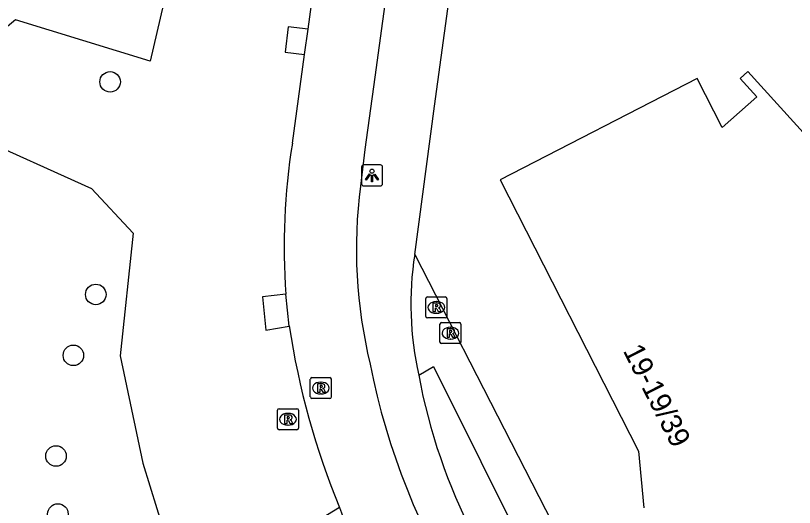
# Model space of a CAD drawing. Extents: x 161402 to 161933, y 381650 to 382313.
# Drawn here: x 161742.85 to 161779.97, y 381978.33 to 382001.78 of the extents above; entities that cross this region are included whole.
import ezdxf

# ---------------------------------------------------------------- set-up
doc = ezdxf.new("R2010")
doc.units = 0
for name, color, linetype in [('IMGEO_Boom', 7, 'Continuous'), ('IMGEO_Groenvoorziening', 7, 'Continuous'), ('IMGEO_Lichtpunt', 7, 'Continuous'), ('IMGEO_Pand', 7, 'Continuous'), ('IMGEO_Pand_nummerreeks', 7, 'Continuous'), ('IMGEO_Rijbaan_lokaal_open', 7, 'Continuous'), ('IMGEO_Rioolput', 7, 'Continuous'), ('IMGEO_Voetpad_open', 7, 'Continuous')]:
    doc.layers.add(name, color=color, linetype=linetype)

msp = doc.modelspace()

# ---------------------------------------------------------------- linework, layer by layer
at = {"layer": 'IMGEO_Boom'}
for centre in [(161747.35, 381998.619), (161746.668, 381988.486), (161745.601, 381985.582), (161744.773, 381980.783), (161744.864, 381978.019)]:
    msp.add_circle(centre, 0.489, dxfattribs=at)
at = {"layer": 'IMGEO_Groenvoorziening'}
msp.add_lwpolyline([(161752.007, 382011.44), (161749.264, 381999.612), (161742.845, 382001.573), (161740.844, 381999.927), (161740.748, 381996.108), (161746.467, 381993.537), (161748.45, 381991.402), (161747.827, 381985.564), (161748.917, 381980.449), (161750.906, 381973.96)], dxfattribs=at)
at = {"layer": 'IMGEO_Lichtpunt'}
for p, q in [((161759.338, 381994.563), (161759.338, 381993.756)), ((161759.338, 381994.563), (161759.338, 381993.756)), ((161760.24, 381994.658), (161759.432, 381994.658)), ((161760.24, 381994.658), (161759.432, 381994.658)), ((161760.334, 381993.756), (161760.334, 381994.563)), ((161760.334, 381993.756), (161760.334, 381994.563)), ((161759.432, 381993.662), (161760.24, 381993.662)), ((161759.432, 381993.662), (161760.24, 381993.662))]:
    msp.add_line(p, q, dxfattribs=at)
for points in [[(161759.712, 381994.227), (161759.751, 381994.199), (161759.563, 381993.937), (161759.525, 381993.964), (161759.712, 381994.227)], [(161759.814, 381994.179), (161759.861, 381994.179), (161759.861, 381993.857), (161759.814, 381993.857), (161759.814, 381994.179)], [(161759.924, 381994.199), (161759.962, 381994.226), (161760.149, 381993.964), (161760.11, 381993.936), (161759.924, 381994.199)]]:
    msp.add_lwpolyline(points, dxfattribs=at)
msp.add_circle((161759.837, 381994.361), 0.0994, dxfattribs=at)
for centre, start, end in [((161759.432, 381994.563), 90, 180), ((161759.432, 381994.563), 90, 180), ((161760.24, 381994.563), 0, 90), ((161760.24, 381994.563), 0, 90), ((161759.432, 381993.756), 180, 270), ((161759.432, 381993.756), 180, 270), ((161760.24, 381993.756), 270, 0), ((161760.24, 381993.756), 270, 360)]:
    msp.add_arc(centre, 0.0946, start, end, dxfattribs=at)
at = {"layer": 'IMGEO_Pand'}
msp.add_lwpolyline([(161780.758, 381965.653), (161791.79, 381971.32), (161790.711, 381973.405), (161794.625, 381975.432), (161794.738, 381975.207), (161795.171, 381975.426), (161788.334, 381988.775), (161786.795, 381987.989), (161785.621, 381990.324), (161785.669, 381990.368), (161777.752, 381999.117), (161777.382, 381998.782), (161778.17, 381997.911), (161776.531, 381996.448), (161775.334, 381998.777), (161765.944, 381993.952), (161772.541, 381981.009), (161772.785, 381978.319)], dxfattribs=at)
at = {"layer": 'IMGEO_Rijbaan_lokaal_open'}
for points in [[(161769.695, 382069.904), (161759.969, 381998.846), (161759.49, 381995.39), (161759.283, 381993.653)], [(161756.786, 382001.123), (161757.438, 382005.955)], [(161756.622, 381999.921), (161756.786, 382001.123)], [(161756.039, 381995.697), (161756.622, 381999.921)], [(161755.89, 381986.981), (161755.73, 381988.499)], [(161758.283, 381978.333), (161750.941, 381973.847)]]:
    msp.add_lwpolyline(points, dxfattribs=at)
for centre, radius, start, end in [((161786.344, 381990.79), 30.699, 170.8031, 184.2806), ((161782.545, 381990.658), 23.454, 172.6635, 193.5519), ((161792.794, 381992.538), 37.32, 188.5628, 202.372), ((161793.302, 381991.816), 34.211, 191.2156, 232.7772), ((161793.148, 381990.522), 36.934, 199.2697, 206.2124)]:
    msp.add_arc(centre, radius, start, end, dxfattribs=at)
at = {"layer": 'IMGEO_Rioolput'}
for p, q in [((161762.401, 381987.44), (161762.401, 381988.292)), ((161762.476, 381988.366), (161763.328, 381988.366)), ((161762.889, 381988.146), (161762.914, 381988.146)), ((161763.402, 381988.292), (161763.402, 381987.44)), ((161762.912, 381987.586), (161762.887, 381987.586)), ((161763.328, 381987.366), (161762.476, 381987.366)), ((161763.074, 381986.215), (161763.074, 381987.067)), ((161763.149, 381987.141), (161764.001, 381987.141)), ((161764.075, 381987.067), (161764.075, 381986.215)), ((161763.562, 381986.921), (161763.587, 381986.921)), ((161763.585, 381986.361), (161763.56, 381986.361)), ((161764.001, 381986.141), (161763.149, 381986.141)), ((161756.895, 381983.597), (161756.895, 381984.449)), ((161756.97, 381984.523), (161757.822, 381984.523)), ((161757.896, 381984.449), (161757.896, 381983.597)), ((161757.383, 381984.303), (161757.408, 381984.303)), ((161757.406, 381983.743), (161757.381, 381983.743)), ((161757.822, 381983.523), (161756.97, 381983.523)), ((161755.329, 381982.111), (161755.329, 381982.963)), ((161755.404, 381983.037), (161756.256, 381983.037)), ((161756.33, 381982.963), (161756.33, 381982.111)), ((161755.817, 381982.817), (161755.842, 381982.817)), ((161755.84, 381982.257), (161755.815, 381982.257)), ((161756.256, 381982.037), (161755.404, 381982.037))]:
    msp.add_line(p, q, dxfattribs=at)
for points in [[(161762.401, 381987.44), (161762.401, 381988.292)], [(161762.476, 381988.366), (161763.328, 381988.366)], [(161763.402, 381988.292), (161763.402, 381987.44)], [(161762.99, 381988.064), (161762.738, 381988.066), (161762.738, 381987.666)], [(161762.738, 381987.666), (161762.862, 381987.666), (161762.862, 381987.828), (161762.873, 381987.828)], [(161762.916, 381987.985), (161762.862, 381987.985), (161762.862, 381987.904)], [(161762.862, 381987.904), (161762.914, 381987.904)], [(161762.92, 381987.799), (161762.991, 381987.666), (161763.131, 381987.666), (161763.066, 381987.792)], [(161763.328, 381987.366), (161762.476, 381987.366)], [(161763.074, 381986.215), (161763.074, 381987.067)], [(161763.149, 381987.141), (161764.001, 381987.141)], [(161764.075, 381987.067), (161764.075, 381986.215)], [(161763.663, 381986.839), (161763.411, 381986.841), (161763.411, 381986.441)], [(161763.589, 381986.76), (161763.535, 381986.76), (161763.535, 381986.679)], [(161763.535, 381986.679), (161763.587, 381986.679)], [(161763.411, 381986.441), (161763.535, 381986.441), (161763.535, 381986.603), (161763.546, 381986.603)], [(161763.593, 381986.574), (161763.664, 381986.441), (161763.804, 381986.441), (161763.739, 381986.567)], [(161764.001, 381986.141), (161763.149, 381986.141)], [(161756.895, 381983.597), (161756.895, 381984.449)], [(161756.97, 381984.523), (161757.822, 381984.523)], [(161757.896, 381984.449), (161757.896, 381983.597)], [(161757.484, 381984.221), (161757.232, 381984.223), (161757.232, 381983.823)], [(161757.41, 381984.142), (161757.356, 381984.142), (161757.356, 381984.061)], [(161757.356, 381984.061), (161757.408, 381984.061)], [(161757.232, 381983.823), (161757.356, 381983.823), (161757.356, 381983.985), (161757.367, 381983.985)], [(161757.414, 381983.956), (161757.485, 381983.823), (161757.625, 381983.823), (161757.56, 381983.949)], [(161757.822, 381983.523), (161756.97, 381983.523)], [(161755.329, 381982.111), (161755.329, 381982.963)], [(161755.404, 381983.037), (161756.256, 381983.037)], [(161756.33, 381982.963), (161756.33, 381982.111)], [(161755.918, 381982.735), (161755.666, 381982.737), (161755.666, 381982.337)], [(161755.844, 381982.656), (161755.79, 381982.656), (161755.79, 381982.575)], [(161755.79, 381982.575), (161755.842, 381982.575)], [(161755.666, 381982.337), (161755.79, 381982.337), (161755.79, 381982.499), (161755.801, 381982.499)], [(161755.848, 381982.47), (161755.919, 381982.337), (161756.059, 381982.337), (161755.994, 381982.463)], [(161756.256, 381982.037), (161755.404, 381982.037)]]:
    msp.add_lwpolyline(points, dxfattribs=at)
for centre, radius, start, end in [((161762.478, 381988.29), 0.0765, 91.552, 178.448), ((161762.478, 381988.29), 0.0765, 91.552, 178.448), ((161763.326, 381988.29), 0.0765, 1.552, 88.448), ((161763.326, 381988.29), 0.0765, 1.552, 88.448), ((161762.872, 381987.775), 0.0533, 26.0293, 88.6989), ((161762.898, 381988.093), 0.19, 274.7715, 282.9687), ((161762.922, 381987.889), 0.0964, 77.0061, 93.1865), ((161762.936, 381987.946), 0.0378, 276.6634, 79.6772), ((161762.989, 381987.954), 0.109, 350.3612, 89.416), ((161762.987, 381987.954), 0.112, 277.5842, 350.9817), ((161762.971, 381987.739), 0.108, 29.5134, 73.7905), ((161762.478, 381987.442), 0.0765, 181.552, 268.448), ((161762.478, 381987.442), 0.0765, 181.552, 268.448), ((161763.326, 381987.442), 0.0765, 271.552, 358.448), ((161763.326, 381987.442), 0.0765, 271.552, 358.448), ((161763.151, 381987.065), 0.0765, 91.552, 178.448), ((161763.151, 381987.065), 0.0765, 91.552, 178.448), ((161763.999, 381987.065), 0.0765, 1.552, 88.448), ((161763.999, 381987.065), 0.0765, 1.552, 88.448), ((161763.571, 381986.868), 0.19, 274.7715, 282.9687), ((161763.595, 381986.664), 0.0964, 77.0061, 93.1865), ((161763.609, 381986.721), 0.0378, 276.6634, 79.6772), ((161763.662, 381986.729), 0.109, 350.3612, 89.416), ((161763.66, 381986.729), 0.112, 277.5842, 350.9817), ((161763.545, 381986.55), 0.0533, 26.0293, 88.6989), ((161763.644, 381986.514), 0.108, 29.5134, 73.7905), ((161763.151, 381986.217), 0.0765, 181.552, 268.448), ((161763.151, 381986.217), 0.0765, 181.552, 268.448), ((161763.999, 381986.217), 0.0765, 271.552, 358.448), ((161763.999, 381986.217), 0.0765, 271.552, 358.448), ((161756.972, 381984.447), 0.0765, 91.552, 178.448), ((161756.972, 381984.447), 0.0765, 91.552, 178.448), ((161757.82, 381984.447), 0.0765, 1.552, 88.448), ((161757.82, 381984.447), 0.0765, 1.552, 88.448), ((161757.392, 381984.25), 0.19, 274.7715, 282.9687), ((161757.416, 381984.046), 0.0964, 77.0061, 93.1865), ((161757.43, 381984.103), 0.0378, 276.6634, 79.6772), ((161757.483, 381984.111), 0.109, 350.3612, 89.416), ((161757.481, 381984.111), 0.112, 277.5842, 350.9817), ((161757.366, 381983.932), 0.0533, 26.0293, 88.6989), ((161757.465, 381983.896), 0.108, 29.5134, 73.7905), ((161756.972, 381983.599), 0.0765, 181.552, 268.448), ((161756.972, 381983.599), 0.0765, 181.552, 268.448), ((161757.82, 381983.599), 0.0765, 271.552, 358.448), ((161757.82, 381983.599), 0.0765, 271.552, 358.448), ((161755.406, 381982.961), 0.0765, 91.552, 178.448), ((161755.406, 381982.961), 0.0765, 91.552, 178.448), ((161756.254, 381982.961), 0.0765, 1.552, 88.448), ((161756.254, 381982.961), 0.0765, 1.552, 88.448), ((161755.826, 381982.764), 0.19, 274.7715, 282.9687), ((161755.85, 381982.56), 0.0964, 77.0061, 93.1865), ((161755.864, 381982.617), 0.0378, 276.6634, 79.6772), ((161755.917, 381982.625), 0.109, 350.3612, 89.416), ((161755.915, 381982.625), 0.112, 277.5842, 350.9817), ((161755.8, 381982.446), 0.0533, 26.0293, 88.6989), ((161755.899, 381982.41), 0.108, 29.5134, 73.7905), ((161755.406, 381982.113), 0.0765, 181.552, 268.448), ((161755.406, 381982.113), 0.0765, 181.552, 268.448), ((161756.254, 381982.113), 0.0765, 271.552, 358.448), ((161756.254, 381982.113), 0.0765, 271.552, 358.448)]:
    msp.add_arc(centre, radius, start, end, dxfattribs=at)
for centre, major_axis, ratio, start_param, end_param in [((161762.888, 381987.866), (-0.387, 0.002), 0.722429, 4.712389, 7.853982), ((161762.913, 381987.866), (-0.39, 0.002), 0.717154, 1.570796, 4.712389), ((161763.561, 381986.641), (-0.387, 0.002), 0.722429, 4.712389, 7.853982), ((161763.586, 381986.641), (-0.39, 0.002), 0.717154, 1.570796, 4.712389), ((161757.382, 381984.023), (-0.387, 0.002), 0.722429, 4.712389, 7.853982), ((161757.407, 381984.023), (-0.39, 0.002), 0.717154, 1.570796, 4.712389), ((161755.816, 381982.537), (-0.387, 0.002), 0.722429, 4.712389, 7.853982), ((161755.841, 381982.537), (-0.39, 0.002), 0.717154, 1.570796, 4.712389)]:
    msp.add_ellipse(centre, major_axis=major_axis, ratio=ratio, start_param=start_param, end_param=end_param, dxfattribs=at)
at = {"layer": 'IMGEO_Voetpad_open'}
for points in [[(161761.87, 381990.395), (161762.821, 381997.456), (161773.703, 382076.916)], [(161756.786, 382001.123), (161755.845, 382001.24), (161755.702, 382000.039), (161756.622, 381999.921)], [(161761.87, 381990.395), (161771.057, 381972.467), (161771.173, 381972.261)], [(161755.73, 381988.499), (161754.618, 381988.369), (161754.774, 381986.776), (161755.89, 381986.981)], [(161762.059, 381984.641), (161762.759, 381985.056), (161769.557, 381971.429)]]:
    msp.add_lwpolyline(points, dxfattribs=at)
for centre, radius, start, end in [((161777.164, 381988.017), 15.478, 171.163, 192.5996), ((161789.276, 381989.692), 27.681, 190.5129, 224.0822)]:
    msp.add_arc(centre, radius, start, end, dxfattribs=at)

# ---------------------------------------------------------------- texts
at = {"layer": 'IMGEO_Pand_nummerreeks'}
msp.add_text('19-19/39', height=1, rotation=297.009, dxfattribs=at).set_placement((161771.78, 381985.806))

doc.saveas('drawing.dxf')
